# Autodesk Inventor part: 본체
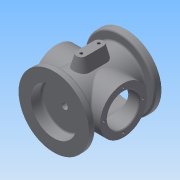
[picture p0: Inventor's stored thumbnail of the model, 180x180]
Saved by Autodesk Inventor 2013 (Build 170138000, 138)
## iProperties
Created: 2018-02
Part Number: 본체
Material: 일반
Document SubType Name: Modeling
Designer: Administrator
Density: 1 g/cm^3
Author: Administrator
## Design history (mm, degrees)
sketch "스케치1"
  geometry: L1 (0, 0)-(0, 54); L2 (0, 54)-(-52.5, 54); L3 (-52.5, 54)-(-52.5, 44); L4 (-52.5, 44)-(-38, 44); L5 (-38, 44)-(-38, 0); L6 (-38, 0)-(0, 0)
  constraints: 12 end point, 3 parallel, 2 perpendicular, 1 vertical
  dimensions: "d0" = 54 distance of L1.start L1.end; "d1" = 10 distance of L2.end L3.end; "d2" = 52.5 distance of L1.end L2.end; "d3" = 76 diameter of L5 L1
revolve "회전1" sketch "스케치1" stored, may be unused: angle "d4" = 90 deg
fillet "모깎기1" dims "d5" = 3
fillet "모깎기2" dims "d6" = 3
sketch "스케치2"
  geometry: C1 r 35 at (0, 0); 1 further point
  constraints: 1 centre point, 1 coincident
  dimensions: "d7" = 70 diameter of C1
extrude "돌출1" join sketch "스케치2" stored distance "d9" = 100; taper "d10" = 0 deg
hole "구멍1" diameter "d13" = 66; stored, may be unused: countersink angle "d17" = 90 deg, drill point angle "d19" = 0 deg; dims "d11" = 10, "d12" = 10, "d14" = 6, "d15" = 74, "d16" = 7, "d18" = 86
hole "구멍2" diameter "d22" = 10; stored, may be unused: countersink angle "d26" = 90 deg, drill point angle "d28" = 0 deg; dims "d20" = 10, "d21" = 10, "d23" = 6, "d24" = 68, "d25" = 16, "d27" = 86
chamfer "모따기1" distance "d29" = 1; stored, may be unused: second distance "d30" = 2, angle "d31" = 45 deg
fillet "모깎기3" dims "d32" = 3
fillet "모깎기4" dims "d33" = 3
hole "구멍3" diameter "d36" = 48; stored, may be unused: countersink angle "d40" = 90 deg, drill point angle "d42" = 0 deg; dims "d34" = 10, "d35" = 10, "d37" = 6, "d38" = 68, "d39" = 16, "d41" = 86
fillet "모깎기6" dims "d44" = 3
node "작업 평면2"
sketch "스케치3"
  geometry: L1 (-7, 13)-(-7, -13); L2 (7, 13)-(7, -13); A1 r 7 centre (0, 13) between (-7, 13) and (7, 13); A2 r 7 centre (0, -13) between (-7, -13) and (7, -13); 2 further points
  constraints: 4 end point, 4 point on circle, 3 tangent, 2 centre point, 2 vertical alignment, 1 equal radius, 1 horizontal alignment, 1 midpoint, 1 parallel
  dimensions: "d47" = 14 diameter of A1; "d49" = 40 dimension on A2 A1
extrude "돌출2" join sketch "스케치3" stored distance "d50" = 100; taper "d51" = 15 deg
sketch "스케치4"
  geometry: A1 r 7 centre (0, -13) between (-7, -13) and (7, -13) reference; A2 r 7 centre (0, 13) between (7, 13) and (-7, 13) reference; 3 further points
  constraints: 2 coincident
hole "구멍4" sketch "스케치4" at (0, 13), (0, -13) diameter "d52" = 4.134; stored, may be unused: countersink angle "d56" = 90 deg, drill point angle "d58" = 118 deg; dims "d53" = 6, "d54" = 68, "d55" = 16, "d57" = 8
chamfer "모따기2" distance "d59" = 1; stored, may be unused: second distance "d60" = 2, angle "d61" = 45 deg
sketch "스케치5"
  geometry: C1 r 35 at (0, 0) reference; 1 further point
  constraints: 1 vertical alignment
  dimensions: "d62" = 29 distance of C1.centre point (0, 29)
hole "구멍5" sketch "스케치5" at (0, 29) diameter "d63" = 3.242; stored, may be unused: countersink angle "d67" = 90 deg, drill point angle "d69" = 118 deg; dims "d64" = 4, "d65" = 68, "d66" = 16, "d68" = 6
sketch "스케치6"
  geometry: C1 r 52.5 at (0, 0) reference; 1 further point
  constraints: 1 vertical alignment
  dimensions: "d73" = 45 distance of point (0, 45) C1.centre
hole "구멍6" sketch "스케치6" at (0, 45) diameter "d74" = 3.242; stored, may be unused: countersink angle "d78" = 90 deg, drill point angle "d80" = 118 deg; dims "d75" = 4, "d76" = 68, "d77" = 16, "d79" = 6
sketch "스케치7"
  geometry: C1 r 41 at (0, 0) reference; C2 r 43 at (0, 0)
  constraints: 1 centre point, 1 coincident, 1 other
  dimensions: "d84" = 86 diameter of C2
feature "엠보싱1" sketch "스케치7" dims "d0" = 54, "d1" = 10, "d2" = 52.5, "d3" = 76, "d87" = 0.5, "d88" = 0
node "솔리드1"
mirror "대칭1"
pattern_circular "원형 패턴1" dims angle "d71" = 360 deg
mirror "대칭2"
pattern_circular "원형 패턴2" dims angle "d82" = 360 deg
other parameters: "d46" = 55
